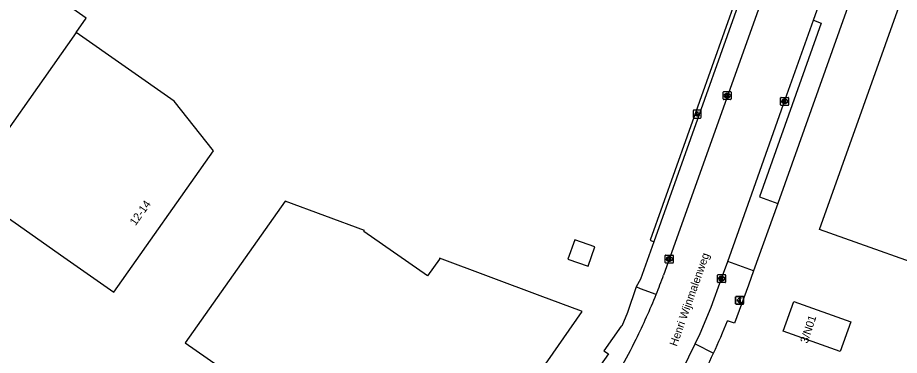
# Model space of a CAD drawing. Extents: x 155018 to 156648, y 383980 to 385733.
# Drawn here: x 155434.7 to 155544.9, y 385132.4 to 385174.7 of the extents above; entities that cross this region are included whole.
import ezdxf

# ---------------------------------------------------------------- set-up
doc = ezdxf.new("R2010")
doc.units = 0
for name, color, linetype in [('IMGEO_Betaalautomaat', 7, 'Continuous'), ('IMGEO_Kolk', 7, 'Continuous'), ('IMGEO_Lichtpunt', 7, 'Continuous'), ('IMGEO_Openbare_ruimte_label', 7, 'Continuous'), ('IMGEO_Pand', 7, 'Continuous'), ('IMGEO_Pand_nummerreeks', 7, 'Continuous'), ('IMGEO_Parkeervlak_open', 7, 'Continuous'), ('IMGEO_Rijbaan_lokaal_gesloten', 7, 'Continuous'), ('IMGEO_Rijbaan_lokaal_open', 7, 'Continuous'), ('IMGEO_Voetpad_open', 7, 'Continuous')]:
    doc.layers.add(name, color=color, linetype=linetype)

msp = doc.modelspace()

# ---------------------------------------------------------------- linework, layer by layer
at = {"layer": 'IMGEO_Betaalautomaat'}
for p, q in [((155524.45, 385138.91), (155524.45, 385139.75)), ((155524.45, 385139.75), (155524.45, 385138.91)), ((155524.52, 385139.83), (155525.36, 385139.83)), ((155525.36, 385139.83), (155524.52, 385139.83)), ((155525.45, 385139.76), (155525.45, 385138.92)), ((155525.45, 385138.92), (155525.45, 385139.76)), ((155525.37, 385138.83), (155524.53, 385138.83)), ((155524.53, 385138.83), (155525.37, 385138.83)), ((155524.73, 385139.29), (155524.73, 385139.36)), ((155524.85, 385139.36), (155524.85, 385139.29)), ((155525.11, 385139.64), (155525.09, 385139.54)), ((155525.1, 385139.13), (155525.12, 385139.04))]:
    msp.add_line(p, q, dxfattribs=at)
for points in [[(155524.73, 385139.36), (155524.66, 385139.36), (155524.66, 385139.43), (155524.74, 385139.43)], [(155524.74, 385139.23), (155524.66, 385139.23), (155524.66, 385139.29), (155524.73, 385139.29)], [(155524.86, 385139.43), (155525.01, 385139.43), (155525.01, 385139.36), (155524.85, 385139.36)], [(155524.85, 385139.29), (155525.01, 385139.29), (155525.01, 385139.23), (155524.87, 385139.23)]]:
    msp.add_lwpolyline(points, dxfattribs=at)
for centre, radius, start, end in [((155524.53, 385139.75), 0.0779, 92.4484, 184.2845), ((155524.53, 385139.75), 0.0779, 92.4484, 184.2845), ((155525.03, 385139.36), 0.293, 73.014, 165.0139), ((155525.37, 385139.75), 0.0779, 2.4484, 94.2845), ((155525.37, 385139.75), 0.0779, 2.4484, 94.2845), ((155524.53, 385138.91), 0.0779, 182.4484, 274.2845), ((155524.53, 385138.91), 0.0779, 182.4484, 274.2845), ((155525, 385139.28), 0.267, 191.8096, 297.0389), ((155525.03, 385139.37), 0.179, 69.3236, 159.5683), ((155525.03, 385139.3), 0.179, 202.7625, 291.8693), ((155525.37, 385138.91), 0.0779, 272.4484, 4.2845), ((155525.37, 385138.91), 0.0779, 272.4484, 4.2845)]:
    msp.add_arc(centre, radius, start, end, dxfattribs=at)
at = {"layer": 'IMGEO_Kolk'}
for p, q in [((155522.89, 385164.53), (155522.89, 385165.38)), ((155522.96, 385165.45), (155523.82, 385165.45)), ((155523.38, 385165.23), (155523.4, 385165.23)), ((155523.89, 385165.38), (155523.89, 385164.53)), ((155523.82, 385164.45), (155522.96, 385164.45)), ((155523.4, 385164.67), (155523.37, 385164.67)), ((155530.07, 385163.8), (155530.07, 385164.66)), ((155530.14, 385164.73), (155531, 385164.73)), ((155530.56, 385164.51), (155530.58, 385164.51)), ((155530.58, 385163.95), (155530.56, 385163.95)), ((155531.07, 385164.66), (155531.07, 385163.8)), ((155531, 385163.73), (155530.14, 385163.73)), ((155515.66, 385144.07), (155515.66, 385144.93)), ((155515.73, 385145), (155516.58, 385145)), ((155516.17, 385144.22), (155516.14, 385144.22)), ((155516.15, 385144.78), (155516.17, 385144.78)), ((155516.66, 385144.93), (155516.66, 385144.07)), ((155516.58, 385144), (155515.73, 385144)), ((155522.19, 385141.62), (155522.19, 385142.48)), ((155522.27, 385142.55), (155523.12, 385142.55)), ((155522.68, 385142.33), (155522.71, 385142.33)), ((155523.2, 385142.48), (155523.2, 385141.62)), ((155523.12, 385141.55), (155522.27, 385141.55)), ((155522.7, 385141.77), (155522.68, 385141.77))]:
    msp.add_line(p, q, dxfattribs=at)
for points in [[(155522.89, 385164.53), (155522.89, 385165.38)], [(155522.96, 385165.45), (155523.82, 385165.45)], [(155523.21, 385165.15), (155523.33, 385165.15), (155523.33, 385165), (155523.46, 385165.15), (155523.63, 385165.15), (155523.48, 385165), (155523.63, 385164.75), (155523.48, 385164.75), (155523.4, 385164.92), (155523.33, 385164.85), (155523.33, 385164.75), (155523.21, 385164.75), (155523.21, 385165.15)], [(155523.89, 385165.38), (155523.89, 385164.53)], [(155523.82, 385164.45), (155522.96, 385164.45)], [(155530.07, 385163.8), (155530.07, 385164.66)], [(155530.14, 385164.73), (155531, 385164.73)], [(155530.39, 385164.43), (155530.51, 385164.43), (155530.51, 385164.28), (155530.64, 385164.43), (155530.81, 385164.43), (155530.66, 385164.28), (155530.81, 385164.03), (155530.66, 385164.03), (155530.58, 385164.19), (155530.51, 385164.13), (155530.51, 385164.03), (155530.39, 385164.03), (155530.39, 385164.43)], [(155531.07, 385164.66), (155531.07, 385163.8)], [(155531, 385163.73), (155530.14, 385163.73)], [(155515.66, 385144.07), (155515.66, 385144.93)], [(155515.73, 385145), (155516.58, 385145)], [(155515.98, 385144.7), (155516.1, 385144.7), (155516.1, 385144.55), (155516.23, 385144.7), (155516.4, 385144.7), (155516.25, 385144.55), (155516.4, 385144.3), (155516.25, 385144.3), (155516.17, 385144.46), (155516.1, 385144.4), (155516.1, 385144.3), (155515.98, 385144.3), (155515.98, 385144.7)], [(155516.66, 385144.93), (155516.66, 385144.07)], [(155516.58, 385144), (155515.73, 385144)], [(155522.19, 385141.62), (155522.19, 385142.48)], [(155522.27, 385142.55), (155523.12, 385142.55)], [(155522.51, 385142.25), (155522.64, 385142.25), (155522.64, 385142.1), (155522.77, 385142.25), (155522.93, 385142.25), (155522.79, 385142.1), (155522.94, 385141.85), (155522.79, 385141.85), (155522.7, 385142.01), (155522.64, 385141.95), (155522.64, 385141.85), (155522.51, 385141.85), (155522.51, 385142.25)], [(155523.2, 385142.48), (155523.2, 385141.62)], [(155523.12, 385141.55), (155522.27, 385141.55)]]:
    msp.add_lwpolyline(points, dxfattribs=at)
for centre, start, end in [((155522.97, 385165.38), 91.552, 178.448), ((155522.97, 385165.38), 91.552, 178.448), ((155523.81, 385165.38), 1.552, 88.448), ((155523.81, 385165.38), 1.552, 88.448), ((155522.97, 385164.53), 181.552, 268.448), ((155522.97, 385164.53), 181.552, 268.448), ((155523.81, 385164.53), 271.552, 358.448), ((155523.81, 385164.53), 271.552, 358.448), ((155530.15, 385164.65), 91.552, 178.448), ((155530.15, 385164.65), 91.552, 178.448), ((155530.99, 385164.65), 1.552, 88.448), ((155530.99, 385164.65), 1.552, 88.448), ((155530.15, 385163.8), 181.552, 268.448), ((155530.15, 385163.8), 181.552, 268.448), ((155530.99, 385163.8), 271.552, 358.448), ((155530.99, 385163.8), 271.552, 358.448), ((155515.73, 385144.92), 91.552, 178.448), ((155515.73, 385144.92), 91.552, 178.448), ((155515.73, 385144.07), 181.552, 268.448), ((155515.73, 385144.07), 181.552, 268.448), ((155516.58, 385144.92), 1.552, 88.448), ((155516.58, 385144.92), 1.552, 88.448), ((155516.58, 385144.07), 271.552, 358.448), ((155516.58, 385144.07), 271.552, 358.448), ((155522.27, 385142.47), 91.552, 178.448), ((155522.27, 385142.47), 91.552, 178.448), ((155523.12, 385142.47), 1.552, 88.448), ((155523.12, 385142.47), 1.552, 88.448), ((155522.27, 385141.63), 181.552, 268.448), ((155522.27, 385141.63), 181.552, 268.448), ((155523.12, 385141.63), 271.552, 358.448), ((155523.12, 385141.63), 271.552, 358.448)]:
    msp.add_arc(centre, 0.0765, start, end, dxfattribs=at)
for centre, major_axis, ratio, start_param, end_param in [((155523.38, 385164.95), (-0.387, 0.002), 0.722429, 4.712389, 7.853982), ((155523.4, 385164.95), (-0.39, 0.002), 0.717154, 1.570796, 4.712389), ((155530.56, 385164.23), (-0.387, 0.002), 0.722429, 4.712389, 7.853982), ((155530.58, 385164.23), (-0.39, 0.002), 0.717154, 1.570796, 4.712389), ((155516.14, 385144.5), (-0.387, 0.002), 0.722429, 4.712389, 7.853982), ((155516.17, 385144.5), (-0.39, 0.002), 0.717154, 1.570796, 4.712389), ((155522.68, 385142.05), (-0.387, 0.002), 0.722429, 4.712389, 7.853982), ((155522.71, 385142.05), (-0.39, 0.002), 0.717154, 1.570796, 4.712389)]:
    msp.add_ellipse(centre, major_axis=major_axis, ratio=ratio, start_param=start_param, end_param=end_param, dxfattribs=at)
at = {"layer": 'IMGEO_Lichtpunt'}
for p, q in [((155519.14, 385163.06), (155519.14, 385162.25)), ((155519.14, 385163.06), (155519.14, 385162.25)), ((155520.04, 385163.15), (155519.24, 385163.15)), ((155520.04, 385163.15), (155519.24, 385163.15)), ((155520.14, 385162.25), (155520.14, 385163.06)), ((155520.14, 385162.25), (155520.14, 385163.06)), ((155519.24, 385162.15), (155520.04, 385162.15)), ((155519.24, 385162.15), (155520.04, 385162.15))]:
    msp.add_line(p, q, dxfattribs=at)
for points in [[(155519.52, 385162.72), (155519.55, 385162.69), (155519.37, 385162.43), (155519.33, 385162.46), (155519.52, 385162.72)], [(155519.62, 385162.67), (155519.66, 385162.67), (155519.66, 385162.35), (155519.62, 385162.35), (155519.62, 385162.67)], [(155519.73, 385162.69), (155519.77, 385162.72), (155519.95, 385162.46), (155519.91, 385162.43), (155519.73, 385162.69)]]:
    msp.add_lwpolyline(points, dxfattribs=at)
msp.add_circle((155519.64, 385162.85), 0.0994, dxfattribs=at)
for centre, start, end in [((155519.24, 385163.06), 90, 180), ((155519.24, 385163.06), 90, 180), ((155520.04, 385163.06), 0, 90), ((155520.04, 385163.06), 0, 90), ((155519.24, 385162.25), 180, 270), ((155519.24, 385162.25), 180, 270), ((155520.04, 385162.25), 270, 0), ((155520.04, 385162.25), 270, 360)]:
    msp.add_arc(centre, 0.0946, start, end, dxfattribs=at)
at = {"layer": 'IMGEO_Pand'}
for points in [[(155442.01, 385172.85), (155443.27, 385174.66), (155413.9, 385195.2), (155370.63, 385133.35), (155367.77, 385129.25), (155364.49, 385131.54), (155359.43, 385135.08), (155348.62, 385119.63), (155349.5, 385119.02), (155349.89, 385116.96), (155349.27, 385116.07), (155368.07, 385102.91), (155368.63, 385103.71), (155385.16, 385092.22), (155424.54, 385148.03), (155428.3, 385153.34)], [(155564.35, 385122.44), (155569.18, 385136.03), (155534.94, 385148.2), (155545.92, 385179.11), (155547.38, 385178.75), (155551.81, 385178.73), (155553.29, 385178.36), (155554, 385180.39), (155574.93, 385172.93), (155575.01, 385172.91), (155581.82, 385170.48), (155577.59, 385158.61), (155588.82, 385154.6), (155575.94, 385118.32), (155564.35, 385122.44)], [(155442.01, 385172.85), (155428.3, 385153.34)], [(155428.3, 385153.34), (155440.51, 385144.72), (155446.72, 385140.34), (155459.18, 385158.04), (155454.27, 385164.27), (155442.01, 385172.85)], [(155497.44, 385126.74), (155500, 385130.4), (155505.27, 385137.93), (155505.17, 385137.99), (155500, 385139.91), (155487.45, 385144.59), (155487.43, 385144.49), (155485.93, 385142.38), (155478, 385147.93), (155478.07, 385148.08), (155468.14, 385151.74), (155455.67, 385134.02), (155466.24, 385126.61), (155468.35, 385129.61), (155476.24, 385124.07), (155474.13, 385121.07), (155487.09, 385111.95), (155492.48, 385119.66), (155492.83, 385120.16), (155492.42, 385120.45), (155496.68, 385126.52), (155497.09, 385126.24), (155497.44, 385126.74)], [(155506.02, 385143.62), (155506.84, 385146.04), (155504.35, 385146.91), (155503.49, 385144.49), (155506.02, 385143.62)], [(155537.52, 385132.91), (155530.39, 385135.47), (155531.74, 385139.17), (155538.86, 385136.63), (155537.52, 385132.91)]]:
    msp.add_lwpolyline(points, dxfattribs=at)
at = {"layer": 'IMGEO_Parkeervlak_open'}
msp.add_lwpolyline([(155514.24, 385146.67), (155512.55, 385141.98), (155512.01, 385141.01)], dxfattribs=at)
at = {"layer": 'IMGEO_Rijbaan_lokaal_gesloten'}
for points in [[(155534.19, 385174.38), (155539.73, 385189.98), (155540.75, 385192.84)], [(155531.64, 385187.95), (155515.45, 385142.5)], [(155523.46, 385144.21), (155526.46, 385152.66), (155530.45, 385163.87), (155534.19, 385174.38)], [(155519.39, 385133.9), (155520.02, 385135.19), (155521.4, 385138.49), (155522.69, 385142.05), (155523.46, 385144.21)], [(155504.46, 385109.35), (155509.68, 385116.82), (155513.64, 385123.17), (155517.04, 385129.07), (155519.39, 385133.9)]]:
    msp.add_lwpolyline(points, dxfattribs=at)
for centre, radius, start, end in [((155440.16, 385169.94), 80.13, 338.1083, 339.9714), ((155442.07, 385169.16), 78.07, 333.6256, 338.1187), ((155441.61, 385169.35), 78.57, 327.5077, 333.6493)]:
    msp.add_arc(centre, radius, start, end, dxfattribs=at)
at = {"layer": 'IMGEO_Rijbaan_lokaal_open'}
for points in [[(155534.19, 385174.38), (155535.15, 385174.02), (155527.45, 385152.29), (155529.71, 385151.46)], [(155529.71, 385151.46), (155526.7, 385143.01)], [(155526.7, 385143.01), (155523.46, 385144.21)]]:
    msp.add_lwpolyline(points, dxfattribs=at)
at = {"layer": 'IMGEO_Voetpad_open'}
for points in [[(155551.45, 385201.4), (155546.6, 385198.73), (155542.42, 385187.25), (155529.71, 385151.46)], [(155529.19, 385190.29), (155513.77, 385146.87), (155514.24, 385146.67)], [(155528.83, 385187.83), (155514.24, 385146.67)], [(155526.7, 385143.01), (155526.06, 385141.21), (155524.3, 385136.46), (155523.43, 385136.78)], [(155512.01, 385141.01), (155510.94, 385137.8), (155510.23, 385136.1), (155510.14, 385136.11), (155507.99, 385133.03), (155508.55, 385132.63), (155500.69, 385121.46), (155500.79, 385121.37), (155500, 385120.25), (155495.74, 385114.25)], [(155514.51, 385140.06), (155512.57, 385140.78), (155512.01, 385141.01)], [(155519.39, 385133.9), (155521.68, 385132.71)]]:
    msp.add_lwpolyline(points, dxfattribs=at)
for centre, radius, start, end in [((155435.94, 385172.05), 94.34, 335.3543, 338.0447), ((155437.43, 385171.44), 92.73, 332.5779, 335.3115)]:
    msp.add_arc(centre, radius, start, end, dxfattribs=at)

# ---------------------------------------------------------------- texts
at = {"layer": 'IMGEO_Openbare_ruimte_label'}
msp.add_text('Henri Wijnmalenweg', height=1, rotation=70.4964, dxfattribs=at).set_placement((155517.09, 385133.5))
at = {"layer": 'IMGEO_Pand_nummerreeks'}
for s, rotation, p in [('12-14', 54.8701, (155449.45, 385148.6)), ('3/N01', 71.6915, (155533.43, 385133.87))]:
    msp.add_text(s, height=1, rotation=rotation, dxfattribs=at).set_placement(p)

doc.saveas('drawing.dxf')
